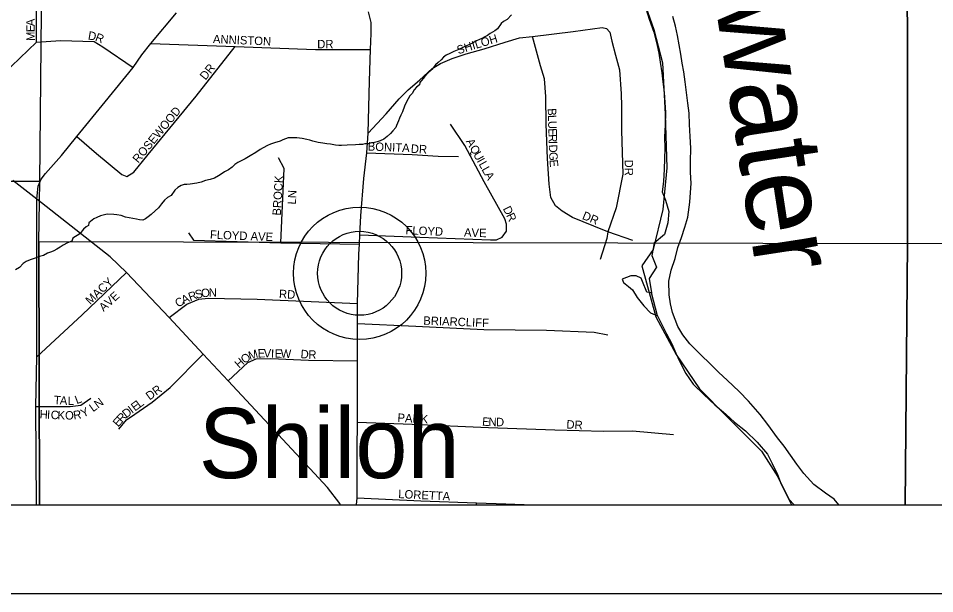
# Model space of a CAD drawing. Extents: x 8.5 to 81.5, y -1.2 to 22.4.
# Drawn here: x 50.196 to 51.227, y 14.351 to 14.998 of the extents above; entities that cross this region are included whole.
import ezdxf

# ---------------------------------------------------------------- set-up
doc = ezdxf.new("R2010")
doc.units = 0
for name, color, linetype in [('GM_X_Corporation', 7, 'Continuous'), ('GM_X_County', 7, 'Continuous'), ('GM_X_County_Road', 7, 'Continuous'), ('GM_X_Major_River', 7, 'Continuous'), ('GM_X_Major_River_Text', 7, 'Continuous'), ('GM_X_Minor_River', 7, 'Continuous'), ('GM_X_Section', 7, 'Continuous'), ('GM_X_State_Route', 7, 'Continuous'), ('GM_X_Township', 7, 'Continuous'), ('GM_X_Township_Road', 7, 'Continuous'), ('GM_X_Township_Subdivision', 7, 'Continuous'), ('GM_X_Township_Subdivision_Text', 7, 'Continuous'), ('GM_X_Unincorporated', 7, 'Continuous'), ('GM_X_Unincorporated_Location', 7, 'Continuous'), ('GM_X_Unincorporated_Text', 7, 'Continuous'), ('SH_Data', 7, 'Continuous')]:
    doc.layers.add(name, color=color, linetype=linetype)

msp = doc.modelspace()

# ---------------------------------------------------------------- linework, layer by layer
at = {"layer": 'GM_X_Corporation'}
msp.add_line((51.0687, 14.4506), (52.1333, 14.4506), dxfattribs=at)
msp.add_lwpolyline([(51.2945, 15.2917), (51.1966, 15.2917), (51.1966, 15.2606), (51.1174, 15.2595), (51.1092, 15.2548), (50.864, 15.2548), (50.8731, 15.1668), (50.882, 15.0975), (50.8955, 15.0291), (50.9111, 14.985), (50.9207, 14.9475), (50.9238, 14.8897), (50.9254, 14.8296), (50.9211, 14.7826), (50.9101, 14.7376), (50.8975, 14.7193), (50.9131, 14.6619), (50.936, 14.6195), (50.9623, 14.5808), (50.9931, 14.55), (51.0319, 14.511), (51.0505, 14.482), (51.0628, 14.457), (51.0687, 14.4506)], dxfattribs=at)
at = {"layer": 'GM_X_County'}
msp.add_lwpolyline([(54.0879, 21.2506), (49.4527, 21.2506), (49.4527, 14.4506), (56.2527, 14.4506), (56.2527, 19.1108)], dxfattribs=at)
at = {"layer": 'GM_X_County_Road'}
for points in [[(50.2169, 14.7944), (50.2183, 14.8088), (50.2218, 14.8168), (50.2267, 14.8231), (50.2448, 14.8435), (50.262, 14.8649), (50.2937, 14.9038), (50.3251, 14.9423), (50.3352, 14.9568), (50.3452, 14.9693), (50.3741, 15.0038)], [(50.5765, 14.4506), (50.5771, 14.4582), (50.5774, 14.5132), (50.5775, 14.5434), (50.5775, 14.5658), (50.5776, 14.6124), (50.5778, 14.6543), (50.5778, 14.677), (50.5793, 14.7323), (50.58, 14.7437), (50.5801, 14.7542), (50.5815, 14.7754), (50.5847, 14.8174), (50.5883, 14.8464), (50.5896, 14.8684), (50.5913, 14.927), (50.5923, 14.9625), (50.5929, 14.9806), (50.593, 14.9928), (50.59, 15.0049)], [(50.2165, 14.4506), (50.2157, 14.5611), (50.2169, 14.6171), (50.2169, 14.7944)]]:
    msp.add_lwpolyline(points, dxfattribs=at)
at = {"layer": 'GM_X_Major_River'}
msp.add_line((50.915, 14.663), (50.9084, 14.6888), dxfattribs=at)
for points in [[(50.9023, 15.0076), (50.9055, 14.9969), (50.9109, 14.9823), (50.9141, 14.9705), (50.9165, 14.9586), (50.9182, 14.9483), (50.9199, 14.9365), (50.9212, 14.9262), (50.9225, 14.9144), (50.9234, 14.9029), (50.924, 14.8919), (50.9237, 14.8778), (50.923, 14.8645), (50.9232, 14.8512), (50.9227, 14.828), (50.9217, 14.8143), (50.9203, 14.8026), (50.9239, 14.793), (50.9278, 14.7804)], [(51.119, 14.4506), (51.1136, 14.4569), (51.1039, 14.4636), (51.0908, 14.4734), (51.0796, 14.4858), (51.0719, 14.4962), (51.0645, 14.5063), (51.0574, 14.5163), (51.05, 14.526), (51.0393, 14.5407), (51.0304, 14.5519), (51.0174, 14.567), (51.007, 14.5778), (50.9936, 14.5907), (50.9839, 14.5992), (50.9742, 14.609), (50.9638, 14.6191), (50.9515, 14.6315), (50.9437, 14.6415), (50.9378, 14.6512), (50.932, 14.6669), (50.9296, 14.6765), (50.9283, 14.6868), (50.9278, 14.702), (50.9303, 14.7145), (50.9348, 14.7277), (50.938, 14.7398), (50.9421, 14.7512), (50.9457, 14.7629), (50.949, 14.7742), (50.9516, 14.7909), (50.9522, 14.8019), (50.9528, 14.8118), (50.9523, 14.8247), (50.9521, 14.8365), (50.9524, 14.8518), (50.9519, 14.8647), (50.951, 14.8784), (50.9505, 14.891), (50.9492, 14.9024), (50.9476, 14.9142), (50.9463, 14.9264), (50.9446, 14.9375), (50.9429, 14.9471), (50.9412, 14.9574), (50.9375, 14.9784), (50.9354, 14.9887), (50.9322, 14.9998)], [(50.9278, 14.7804), (50.9268, 14.7678), (50.9228, 14.7546), (50.9112, 14.7449), (50.9086, 14.7309), (50.9141, 14.7179), (50.9058, 14.7051), (50.9084, 14.6888)], [(50.9084, 14.6888), (50.9032, 14.6895), (50.9014, 14.6934), (50.8996, 14.698), (50.8967, 14.7053), (50.8911, 14.7081), (50.885, 14.7082), (50.8754, 14.7042), (50.8769, 14.7004), (50.8825, 14.6961), (50.887, 14.6922), (50.8921, 14.6837), (50.8995, 14.6744), (50.9073, 14.6666), (50.915, 14.663)], [(50.915, 14.663), (50.9251, 14.6427), (50.931, 14.6315), (50.9357, 14.6212), (50.94, 14.6112), (50.947, 14.5981), (50.9551, 14.5861), (50.967, 14.5745), (50.9797, 14.5628), (50.9921, 14.5523), (51.0018, 14.5433), (51.0141, 14.5336), (51.0271, 14.5211), (51.0387, 14.5076), (51.0441, 14.4968), (51.05, 14.4845), (51.0543, 14.4738), (51.0594, 14.4634), (51.0645, 14.4526), (51.0657, 14.4506)]]:
    msp.add_lwpolyline(points, dxfattribs=at)
at = {"layer": 'GM_X_Minor_River'}
for points in [[(50.7509, 15.0015), (50.7459, 14.9962), (50.742, 14.994), (50.7393, 14.9918), (50.735, 14.9858), (50.732, 14.9836), (50.727, 14.9806), (50.7239, 14.9784), (50.7208, 14.977), (50.7174, 14.9751), (50.7147, 14.9737), (50.7116, 14.9722), (50.707, 14.9696), (50.697, 14.9653), (50.6917, 14.9627), (50.6859, 14.9605), (50.6813, 14.9583), (50.6775, 14.9561), (50.6744, 14.9539), (50.6717, 14.9509), (50.6682, 14.948), (50.6655, 14.9453), (50.6612, 14.9401), (50.6566, 14.936), (50.6531, 14.9319), (50.6477, 14.9255), (50.6472, 14.9229), (50.6441, 14.9203), (50.6414, 14.9173), (50.639, 14.9132), (50.6363, 14.9105), (50.6347, 14.9071), (50.6316, 14.9015), (50.6304, 14.8989), (50.6284, 14.8924), (50.6264, 14.8887), (50.6248, 14.8853), (50.6236, 14.8823), (50.6216, 14.8773), (50.6208, 14.8747), (50.6173, 14.8713), (50.6146, 14.868), (50.6111, 14.8646), (50.6072, 14.8617), (50.603, 14.8598), (50.5996, 14.8588), (50.5969, 14.8581), (50.5935, 14.8577), (50.5893, 14.8567), (50.5859, 14.8564), (50.5832, 14.8557), (50.5794, 14.8557), (50.5752, 14.8554), (50.5661, 14.8549), (50.5597, 14.8546), (50.5566, 14.8547), (50.5529, 14.8551), (50.5472, 14.856), (50.543, 14.8565), (50.5385, 14.8573), (50.5332, 14.8582), (50.5275, 14.8594), (50.5241, 14.8607), (50.5207, 14.8615), (50.5154, 14.8627), (50.5094, 14.8632), (50.5033, 14.8634), (50.4995, 14.8631), (50.4938, 14.8609), (50.4907, 14.8594), (50.4842, 14.8577), (50.4796, 14.8562), (50.4762, 14.8548), (50.4716, 14.8522), (50.4681, 14.85), (50.4631, 14.8467), (50.457, 14.843)], [(50.457, 14.843), (50.4512, 14.8397), (50.4466, 14.8375), (50.4432, 14.8356), (50.4397, 14.8334), (50.4366, 14.8304), (50.4324, 14.8271), (50.4281, 14.8249), (50.4243, 14.8223), (50.4212, 14.8205), (50.4166, 14.8179), (50.412, 14.8165), (50.4067, 14.8151), (50.4017, 14.8133), (50.3968, 14.8122), (50.3895, 14.8112), (50.3857, 14.8109), (50.3827, 14.8106), (50.3793, 14.8095), (50.3754, 14.8073), (50.3723, 14.8043), (50.368, 14.7983), (50.3638, 14.7961), (50.3607, 14.7931), (50.3572, 14.789), (50.3537, 14.7845), (50.3502, 14.7812), (50.3456, 14.7771), (50.3421, 14.7745), (50.339, 14.7723), (50.3363, 14.7708), (50.3325, 14.7709), (50.3291, 14.7717), (50.3167, 14.7742), (50.3118, 14.7759), (50.3069, 14.7767), (50.3035, 14.7772), (50.2959, 14.7773), (50.2886, 14.7756), (50.2844, 14.7737), (50.281, 14.7723), (50.2756, 14.7678), (50.2751, 14.7648), (50.2724, 14.7633), (50.2693, 14.7607), (50.2654, 14.7551), (50.2574, 14.7503), (50.2562, 14.7469), (50.2516, 14.7451), (50.2466, 14.7425), (50.2431, 14.7403), (50.2393, 14.7381), (50.2362, 14.7363), (50.2335, 14.7352), (50.2289, 14.7337), (50.2243, 14.7308), (50.2198, 14.7297), (50.2163, 14.7283), (50.2094, 14.7261), (50.2048, 14.7243), (50.2014, 14.7221), (50.1975, 14.7176), (50.1929, 14.7147)]]:
    msp.add_lwpolyline(points, dxfattribs=at)
at = {"layer": 'GM_X_Section'}
for p, q in [((50.2199, 14.4506), (51.1937, 14.4506)), ((51.1937, 14.4506), (52.195, 14.4506))]:
    msp.add_line(p, q, dxfattribs=at)
for points in [[(49.4527, 14.8223), (50.2203, 14.8143), (50.2298, 15.7659), (49.4527, 15.7683)], [(49.4527, 14.8223), (49.4527, 14.4506), (50.2199, 14.4506)], [(50.2199, 14.4506), (50.219, 14.7462), (50.2203, 14.8143), (49.4527, 14.8223)], [(51.1937, 14.4506), (51.1961, 14.7442), (50.219, 14.7462), (50.2199, 14.4506)], [(52.195, 14.4506), (52.1975, 14.7482), (51.1961, 14.7442), (51.1937, 14.4506)]]:
    msp.add_lwpolyline(points, dxfattribs=at)
for points in [[(50.2298, 15.7659), (51.1955, 15.7645), (51.1961, 14.7442), (50.219, 14.7462), (50.2203, 14.8143)], [(51.1955, 15.7645), (52.2033, 15.7642), (52.1975, 14.7482), (51.1961, 14.7442)]]:
    msp.add_lwpolyline(points, close=True, dxfattribs=at)
at = {"layer": 'GM_X_State_Route'}
msp.add_lwpolyline([(50.5585, 14.4506), (50.5576, 14.4519), (50.5438, 14.4699), (50.524, 14.4914), (50.4321, 14.5898), (50.4041, 14.6199), (50.3659, 14.6612), (50.3179, 14.7117), (50.2995, 14.7293), (50.2169, 14.7944), (50.1899, 14.8152)], dxfattribs=at)
at = {"layer": 'GM_X_Township'}
msp.add_lwpolyline([(49.4527, 15.7601), (49.4527, 14.4506), (54.4602, 14.4506)], dxfattribs=at)
at = {"layer": 'GM_X_Township_Road'}
msp.add_lwpolyline([(50.7114, 14.4506), (50.7114, 14.4528)], dxfattribs=at)
at = {"layer": 'GM_X_Township_Subdivision'}
for points in [[(50.2164, 14.9709), (50.2167, 14.9903), (50.2157, 15.0601), (50.2167, 15.0876)], [(50.5896, 14.8684), (50.61, 14.8901), (50.6246, 14.9071), (50.6345, 14.9173), (50.6475, 14.9283), (50.6617, 14.9411), (50.6709, 14.9468), (50.6841, 14.9525), (50.6999, 14.9578), (50.72, 14.9635), (50.7439, 14.971), (50.7597, 14.9757), (50.7746, 14.9772), (50.8203, 14.9828), (50.8528, 14.9873), (50.8578, 14.9862), (50.8616, 14.982), (50.8637, 14.9719), (50.8679, 14.9563), (50.8723, 14.9397), (50.8742, 14.9129), (50.8747, 14.899), (50.8747, 14.8714), (50.8761, 14.8223), (50.8685, 14.7846), (50.8593, 14.7577), (50.858, 14.7501), (50.8507, 14.7265)], [(50.8874, 14.7477), (50.8593, 14.7577), (50.8433, 14.7638), (50.8193, 14.7735), (50.808, 14.7809), (50.8003, 14.7869), (50.7952, 14.796), (50.7931, 14.8112), (50.7915, 14.8402), (50.79, 14.8788), (50.7896, 14.9098), (50.7878, 14.9297), (50.7833, 14.9444), (50.7746, 14.9772)], [(50.1177, 14.8754), (50.1694, 14.9259), (50.2164, 14.9709), (50.2436, 14.9728), (50.2814, 14.9717), (50.2912, 14.9655), (50.3251, 14.9423)], [(50.262, 14.8649), (50.2842, 14.8457), (50.3126, 14.8219), (50.3181, 14.8197), (50.3259, 14.8248), (50.342, 14.8447), (50.3961, 14.9102), (50.44, 14.966)], [(50.3452, 14.9693), (50.44, 14.966), (50.5302, 14.9625), (50.5923, 14.9625)], [(50.7453, 14.7581), (50.7453, 14.7661), (50.7434, 14.772), (50.7202, 14.8139), (50.6985, 14.8545), (50.6824, 14.8787)], [(50.5883, 14.8464), (50.6392, 14.8445), (50.6683, 14.8427), (50.6913, 14.8422)], [(50.4914, 14.745), (50.4953, 14.8286), (50.4888, 14.8408)], [(50.3875, 14.7564), (50.3932, 14.7483), (50.4914, 14.745), (50.58, 14.7437)], [(50.5801, 14.7542), (50.6477, 14.7515), (50.7273, 14.7486), (50.7341, 14.7484), (50.7402, 14.7515), (50.7453, 14.7581)], [(50.2169, 14.6171), (50.2681, 14.6643), (50.3179, 14.7117)], [(50.3659, 14.6612), (50.3858, 14.6763), (50.3993, 14.6817), (50.4097, 14.683), (50.4649, 14.6818), (50.5778, 14.677)], [(50.5778, 14.6543), (50.6433, 14.6516), (50.7199, 14.6477), (50.7902, 14.647), (50.8437, 14.6448), (50.8592, 14.6415)], [(50.3093, 14.5356), (50.3178, 14.5461), (50.3272, 14.5526), (50.3465, 14.5661), (50.3668, 14.5824), (50.4041, 14.6199)], [(50.4321, 14.5898), (50.4544, 14.6107), (50.4635, 14.6147), (50.4801, 14.6149), (50.5224, 14.6132), (50.5776, 14.6124)], [(50.2157, 14.5611), (50.2545, 14.5609), (50.2664, 14.5625), (50.2775, 14.5705)], [(50.5775, 14.5434), (50.6392, 14.5412), (50.7249, 14.5375), (50.7997, 14.535), (50.8542, 14.5332), (50.8871, 14.5337), (50.9331, 14.5295)], [(50.5771, 14.4582), (50.6489, 14.455), (50.7114, 14.4528), (50.7445, 14.4517), (50.7751, 14.4506)]]:
    msp.add_lwpolyline(points, dxfattribs=at)
at = {"layer": 'GM_X_Unincorporated'}
for radius in [0.0744, 0.0472]:
    msp.add_circle((50.58, 14.7109), radius, dxfattribs=at)
at = {"layer": 'GM_X_Unincorporated_Location'}
msp.add_line((50.58, 14.7109), (50.58, 14.7109), dxfattribs=at)
at = {"layer": 'SH_Data'}
for p, q in [((49.4527, 14.4506), (56.2527, 14.4506)), ((49.3527, 14.3506), (56.3527, 14.3506))]:
    msp.add_line(p, q, dxfattribs=at)

# ---------------------------------------------------------------- texts
at = {"layer": 'GM_X_Major_River_Text'}
msp.add_text('Stillwater', height=0.09478, rotation=278.71, dxfattribs=at).set_placement((50.949, 15.216))
at = {"layer": 'GM_X_Township_Subdivision_Text'}
for s, rotation, p in [('A', 90.4372, (50.2145, 14.9888)), ('E', 90.4468, (50.2146, 14.9822)), ('M', 90.4371, (50.2147, 14.9722)), ('D', 350.491, (50.274, 14.974)), ('R', 339.0375, (50.2818, 14.9727)), ('ANNISTON', 357.5787, (50.4149, 14.9698)), ('SHILOH', 17.0189, (50.691, 14.9572)), ('DR', 0, (50.5323, 14.964)), ('DR', 51.3366, (50.4067, 14.9275)), ('ROSEWOOD', 50.5603, (50.331, 14.8342)), ('B', 271.7247, (50.7916, 14.8964)), ('L', 271.7216, (50.7918, 14.8889)), ('U', 271.7271, (50.792, 14.8822)), ('E', 271.7216, (50.7923, 14.8739)), ('R', 271.7247, (50.7925, 14.8672)), ('BONITA', 357.7987, (50.589, 14.849)), ('DR', 356.9776, (50.6374, 14.8465)), ('A', 298.1291, (50.6993, 14.8594)), ('Q', 299.2114, (50.7034, 14.8519)), ('I', 271.721, (50.7927, 14.8597)), ('D', 271.7053, (50.7928, 14.8556)), ('U', 299.2731, (50.7074, 14.8446)), ('G', 272.7102, (50.7931, 14.8471)), ('I', 299.2244, (50.7115, 14.8373)), ('L', 299.2473, (50.7136, 14.8337)), ('E', 274.8693, (50.7935, 14.8384)), ('DR', 270, (50.8782, 14.8388)), ('L', 299.2639, (50.7168, 14.8278)), ('A', 299.2542, (50.7201, 14.822)), ('BROCK', 86.4208, (50.4913, 14.7756)), ('LN', 86.989, (50.5083, 14.7881)), ('D', 296.3402, (50.7409, 14.7836)), ('DR', 337.6179, (50.8296, 14.7722)), ('R', 294.5445, (50.7446, 14.7762)), ('FLOYD', 357.5071, (50.6315, 14.7548)), ('AVE', 358.0261, (50.6973, 14.7523)), ('FLOYD AVE', 357.7959, (50.4115, 14.7498)), ('MACY', 43.0225, (50.2769, 14.6751)), ('AVE', 42.2752, (50.292, 14.6673)), ('R', 20.34, (50.3894, 14.6795)), ('S', 13.7646, (50.3961, 14.6821)), ('O', 7.4069, (50.4023, 14.6836)), ('N', 0.9836, (50.4103, 14.6846)), ('RD', 356.989, (50.4891, 14.6831)), ('C', 34.4848, (50.3762, 14.672)), ('A', 25.7537, (50.3821, 14.676)), ('BRIARCLIFF', 357.8535, (50.6515, 14.6531)), ('H', 41.1181, (50.4444, 14.6035)), ('O', 35.6063, (50.4505, 14.6088)), ('M', 17.0813, (50.4565, 14.6133)), ('E', 1.3386, (50.4654, 14.6161)), ('V', 358.929, (50.472, 14.6163)), ('I', 358.9067, (50.4803, 14.6161)), ('E', 358.9395, (50.4845, 14.616)), ('W', 358.9238, (50.4911, 14.6159)), ('D', 355.4487, (50.5133, 14.6156)), ('R', 358.9594, (50.5222, 14.6149)), ('DR', 36.2589, (50.3438, 14.5677)), ('T', 355.6243, (50.2358, 14.5639)), ('A', 355.6348, (50.2425, 14.5634)), ('L', 1.2128, (50.2518, 14.5628)), ('L', 20.5042, (50.2618, 14.5636)), ('N', 36.8177, (50.2857, 14.5585)), ('E', 36.8739, (50.3273, 14.5553)), ('L', 36.859, (50.3327, 14.5593)), ('H', 357.2009, (50.2199, 14.5477)), ('I', 357.2045, (50.2282, 14.5473)), ('C', 357.2482, (50.2324, 14.5471)), ('K', 358.0337, (50.24, 14.5467)), ('O', 0.162, (50.2487, 14.5464)), ('R', 8.011, (50.2585, 14.5465)), ('Y', 25.885, (50.269, 14.5485)), ('L', 35.6771, (50.2801, 14.5545)), ('R', 47.955, (50.3128, 14.5423)), ('D', 38.868, (50.3176, 14.5476)), ('I', 36.8437, (50.324, 14.5528)), ('E', 48.8475, (50.3085, 14.5374)), ('PARK', 356.9075, (50.6224, 14.5439)), ('E', 354.8575, (50.7175, 14.5397)), ('N', 358.7848, (50.7249, 14.5391)), ('D', 359.9915, (50.7334, 14.5389)), ('DR', 356.9884, (50.8124, 14.5364)), ('LORETTA', 357.3171, (50.6233, 14.4581))]:
    msp.add_text(s, height=0.00947, rotation=rotation, dxfattribs=at).set_placement(p)
at = {"layer": 'GM_X_Unincorporated_Text'}
msp.add_text('Shiloh', height=0.07898, rotation=0, dxfattribs=at).set_placement((50.399, 14.4805))

doc.saveas('drawing.dxf')
